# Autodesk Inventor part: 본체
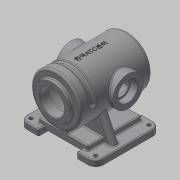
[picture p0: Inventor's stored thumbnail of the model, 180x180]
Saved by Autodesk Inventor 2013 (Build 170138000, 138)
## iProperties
Created: 2015-10
Part Number: 본체
Document SubType Name: Modeling
Designer: mdu
Density: 2.71 g/cm^3
Material: 알루미늄 6061
Mass: 4592.12 g
Surface Area: 2715.66 cm^2
Volume: 1694.51 cm^3
Author: mdu
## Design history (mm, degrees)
sketch "스케치1"
  geometry: L1 (-100, 85)-(-50, 85); L2 (-50, 85)-(-50, -85); L3 (-50, -85)-(-100, -85); L4 (-100, -85)-(-100, 85); L5 (50, 85)-(100, 85); L6 (100, 85)-(100, -85); L7 (100, -85)-(50, -85); L8 (50, -85)-(50, 85); 3 further points
  constraints: 16 end point, 4 parallel, 2 equal length, 2 horizontal, 2 horizontal alignment, 2 midpoint, 2 perpendicular
  dimensions: "d0" = 100 distance between parallel lines of L8 L2; "d1" = 170 distance of L3.end L1.start; "d3" = 200 distance between parallel lines of L6 L4; "d4" = 50 distance from line of point (0, 0) L2 (= 0.5 x d0)
extrude "돌출1" new body sketch "스케치1" distance "d5" = 16; taper "d6" = 0 deg
node "작업 평면1"
sketch "스케치2"
  geometry: L1 (-65, 70)-(65, 70); L2 (65, 70)-(65, -70); L3 (65, -70)-(-65, -70); L4 (-65, -70)-(-65, 70); 3 further points
  constraints: 8 end point, 2 midpoint, 2 parallel, 1 horizontal, 1 horizontal alignment, 1 perpendicular, 1 vertical alignment
  dimensions: "d8" = 130 distance of L2.end L3.end; "d9" = 140 distance of L1.end L2.end
extrude "돌출2" join sketch "스케치2" distance "d10" = 20; taper "d11" = 0 deg
sketch "스케치3"
  geometry: L1 (-100, 110)-(100, 110); L2 (85, 0)-(-85, 0) reference; L3 (100, 110)-(100, 175); L4 (100, 175)-(-90, 175); L5 (-90, 175)-(-90, 156); L6 (-90, 156)-(-100, 156); L7 (-100, 156)-(-100, 110); L8 (90, 110)-(90, 165); L9 (90, 165)-(-75, 165); L10 (-75, 165)-(-75, 110); L11 (-100, 142.5)-(-75, 142.5); 3 further points
  constraints: 20 end point, 5 perpendicular, 4 parallel, 4 point on line, 2 midpoint, 1 horizontal, 1 vertical alignment
  dimensions: "d12" = 110 distance from line of L2 L1.end; "d13" = 200 distance of L1.start L1.end; "d14" = 130 diameter of L4 L1; "d15" = 92 diameter of L6 L1; "d16" = 10 distance of L5.end L6.end; "d42" = 110 diameter of L9 L1; "d43" = 10 distance between parallel lines of L3 L8; "d44" = 25 distance between parallel lines of L10 L7; "d45" = 65 diameter of L11 L1
revolve "회전1" sketch "스케치3" stored, may be unused: angle "d17" = 90 deg
sketch "스케치4"
  geometry: L1 (-50, 70)-(50, 70) reference; L2 (50, -70)-(-50, -70) reference; L3 (-10, 70)-(-10, -70); L4 (10, -70)-(10, 70); 1 further point
  constraints: 4 end point, 4 point on line, 2 perpendicular
  dimensions: "d18" = 20 distance between parallel lines of L4 L3; "d19" = 10 distance from line of point (0, 0) L3
extrude "돌출3" join sketch "스케치4" stored distance "d20" = 10; taper "d21" = 0 deg
node "작업 평면2"
sketch "스케치5"
  geometry: L1 (-50, -8)-(0, -8) reference; L2 (100, -8)-(150, -8) reference; L3 (-40, -8)-(-8.943, -74.601); L4 (140, -8)-(108.943, -74.601); L5 (-50, 8)-(-50, -8) reference; L6 (150, 8)-(150, -8) reference; A1 r 65 centre (50, -102) between (-8.943, -74.601) and (108.943, -74.601) reference; 1 further point
  constraints: 4 end point, 2 point on circle, 2 point on line, 1 equal length
  dimensions: "d23" = 10 distance from line of L3.start L5; "d24" = 10 distance from line of L4.start L6; "d25" = 25 deg angle of L3 L5
feature "리브1" sketch "스케치5" dims "d26" = 1, "d27" = 20, "d28" = 0
node "작업 평면3"
sketch "스케치6"
  geometry: L1 (100, 156)-(100, 64) reference; C1 r 40 at (-25, 110); 2 further points
  constraints: 1 centre point, 1 horizontal alignment, 1 midpoint
  dimensions: "d37" = 80 diameter of C1; "d38" = 125 distance from line of C1.centre L1
extrude "돌출4" join sketch "스케치6" stored distance "d39" = 10; taper "d40" = 0 deg
hole "구멍1" diameter "d48" = 42; stored, may be unused: countersink angle "d52" = 90 deg, drill point angle "d54" = 118 deg; dims "d46" = 10, "d47" = 10, "d49" = 6, "d50" = 52, "d51" = 18, "d53" = 8
sketch "스케치7"
  geometry: C1 r 40 at (0, 0) reference; 2 further points
  constraints: 1 horizontal alignment
  dimensions: "d55" = 32.5 distance of point (32.5, 0) C1.centre
hole "구멍2" sketch "스케치7" at (32.5, 0) diameter "d56" = 3.242; stored, may be unused: countersink angle "d60" = 90 deg, drill point angle "d62" = 118 deg; dims "d57" = 11, "d58" = 52, "d59" = 18, "d61" = 13
sketch "스케치8"
  geometry: C1 r 46 at (0, 0) reference; 2 further points
  constraints: 1 vertical alignment
  dimensions: "d66" = 39 distance of C1.centre point (0, 39)
hole "구멍3" sketch "스케치8" at (0, 39) diameter "d67" = 3.242; stored, may be unused: countersink angle "d71" = 90 deg, drill point angle "d73" = 118 deg; dims "d68" = 11, "d69" = 52, "d70" = 18, "d72" = 13
fillet "모깎기7" dims "d77" = 20, "d78" = 5, "d79" = 3, "d80" = 10, "d107" = 10
fillet "모깎기8" dims "d81" = 3
fillet "모깎기9" dims "d82" = 3
fillet "모깎기10" dims "d83" = 3, "d84" = 0.3
chamfer "모따기1" distance "d85" = 1; stored, may be unused: second distance "d86" = 2, angle "d87" = 45 deg
node "작업 평면4"
sketch "스케치10"
  geometry: 5 further points
  constraints: 2 horizontal alignment, 2 vertical alignment
  dimensions: "d90" = 170 distance of point (85, 70) point (-85, 70); "d91" = 140 distance of point (-85, 70) point (-85, -70); "d92" = 70 vertical distance of point (0, 0) point (-85, -70) (= 0.5 x d91); "d93" = 85 horizontal distance of point (0, 0) point (-85, 70) (= 0.5 x d90)
hole "구멍4" sketch "스케치10" at (-85, 70), (85, 70), (85, -70), (-85, -70) diameter "d94" = 10; stored, may be unused: countersink angle "d98" = 90 deg, drill point angle "d100" = 118 deg; dims "d95" = 6, "d96" = 4, "d97" = 2, "d99" = 8
node "작업 평면5"
sketch "스케치12" dims "d22" = -90
  geometry: L1 (-65, -90)-(65, -90) reference; L2 (65, 85)-(-65, 85) reference; L3 (0, -90)-(0, 85); 3 further points
  constraints: 3 midpoint, 2 end point, 1 coincident, 1 other
feature "엠보싱3" sketch "스케치12" dims "d105" = 1, "d106" = 0
node "작업축1"
sketch "스케치13"
  geometry: L1 (-85, 175)-(90, 175) reference; L2 (-65, 175)-(-50, 175); L3 (-50, 175)-(-50, 170); L4 (-50, 170)-(-65, 170); L5 (-65, 170)-(-65, 175); L6 (-90, 50)-(-90, 170) reference; L7 (-140, 110)-(140, 110) reference; 1 further point
  constraints: 8 end point, 2 parallel, 1 horizontal, 1 perpendicular, 1 point on line
  dimensions: "d108" = 25 distance between parallel lines of L5 L6; "d109" = 15 distance of L3.end L4.end; "d110" = 5 distance of L2.end L3.end
revolve "회전2" sketch "스케치13" stored, may be unused: angle "d111" = 180 deg
fillet "모깎기11" dims "d112" = 5
fillet "모깎기12" dims "d113" = 5
fillet "모깎기13" dims "d114" = 3
node "솔리드1"
mirror "대칭1"
pattern_circular "원형 패턴1" dims angle "d64" = 360 deg
mirror "대칭3"
pattern_circular "원형 패턴2" dims angle "d75" = 360 deg
other parameters: "d7" = 8, "d36" = -75
